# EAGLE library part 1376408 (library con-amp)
DDR1 & DDR2 SODIMM SOCKET 0.6mm Pitch 200 Pos. Standard Profile, Standard Type (used on Kontron X-Board) Source: http://catalog.tycoelectronics.com .. JPN_CD_1376408_S.pdf
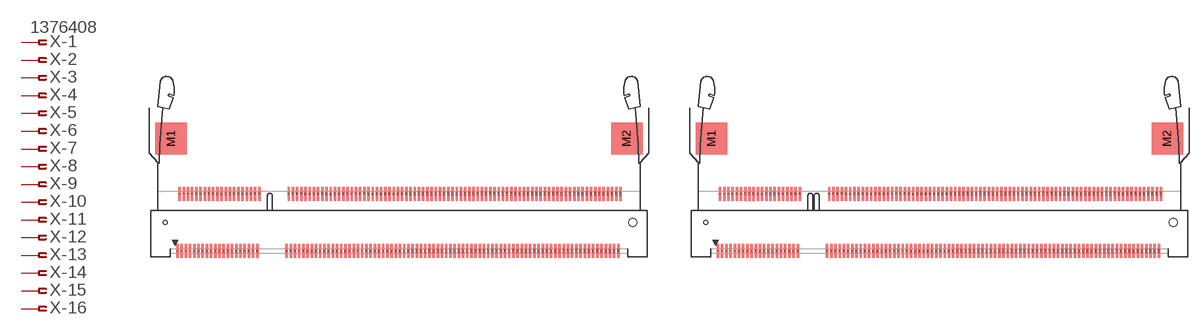
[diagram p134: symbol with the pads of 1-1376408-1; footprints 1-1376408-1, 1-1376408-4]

Designator prefix X; gates -1=PIN-FV -2=PIN-F -3=PIN-F -4=PIN-F -5=PIN-F -6=PIN-F -7=PIN-F -8=PIN-F -9=PIN-F -10=PIN-F -11=PIN-F -12=PIN-F -13=PIN-F -14=PIN-F -15=PIN-F -16=PIN-F -17=PIN-F -18=PIN-F -19=PIN-F -20=PIN-F -21=PIN-F -22=PIN-F -23=PIN-F -24=PIN-F -25=PIN-F -26=PIN-F -27=PIN-F -28=PIN-F -29=PIN-F -30=PIN-F -31=PIN-F -32=PIN-F -33=PIN-F -34=PIN-F -35=PIN-F -36=PIN-F -37=PIN-F -38=PIN-F -39=PIN-F -40=PIN-F -41=PIN-F -42=PIN-F -43=PIN-F -44=PIN-F -45=PIN-F -46=PIN-F -47=PIN-F -48=PIN-F -49=PIN-F -50=PIN-F -51=PIN-F -52=PIN-F -53=PIN-F -54=PIN-F -55=PIN-F -56=PIN-F -57=PIN-F -58=PIN-F -59=PIN-F -60=PIN-F -61=PIN-F -62=PIN-F -63=PIN-F -64=PIN-F -65=PIN-F -66=PIN-F -67=PIN-F -68=PIN-F -69=PIN-F -70=PIN-F -71=PIN-F -72=PIN-F -73=PIN-F -74=PIN-F -75=PIN-F -76=PIN-F -77=PIN-F -78=PIN-F -79=PIN-F -80=PIN-F -81=PIN-F -82=PIN-F -83=PIN-F -84=PIN-F -85=PIN-F -86=PIN-F -87=PIN-F -88=PIN-F -89=PIN-F -90=PIN-F -91=PIN-F -92=PIN-F -93=PIN-F -94=PIN-F -95=PIN-F -96=PIN-F -97=PIN-F -98=PIN-F -99=PIN-F -100=PIN-F -101=PIN-F -102=PIN-F -103=PIN-F -104=PIN-F -105=PIN-F -106=PIN-F -107=PIN-F -108=PIN-F -109=PIN-F -110=PIN-F -111=PIN-F -112=PIN-F -113=PIN-F -114=PIN-F -115=PIN-F -116=PIN-F -117=PIN-F -118=PIN-F -119=PIN-F -120=PIN-F -121=PIN-F -122=PIN-F -123=PIN-F -124=PIN-F -125=PIN-F -126=PIN-F -127=PIN-F -128=PIN-F -129=PIN-F -130=PIN-F -131=PIN-F -132=PIN-F -133=PIN-F -134=PIN-F -135=PIN-F -136=PIN-F -137=PIN-F -138=PIN-F -139=PIN-F -140=PIN-F -141=PIN-F -142=PIN-F -143=PIN-F -144=PIN-F -145=PIN-F -146=PIN-F -147=PIN-F -148=PIN-F -149=PIN-F -150=PIN-F -151=PIN-F -152=PIN-F -153=PIN-F -154=PIN-F -155=PIN-F -156=PIN-F -157=PIN-F -158=PIN-F -159=PIN-F -160=PIN-F -161=PIN-F -162=PIN-F -163=PIN-F -164=PIN-F -165=PIN-F -166=PIN-F -167=PIN-F -168=PIN-F -169=PIN-F -170=PIN-F -171=PIN-F -172=PIN-F -173=PIN-F -174=PIN-F -175=PIN-F -176=PIN-F -177=PIN-F -178=PIN-F -179=PIN-F -180=PIN-F -181=PIN-F -182=PIN-F -183=PIN-F -184=PIN-F -185=PIN-F -186=PIN-F -187=PIN-F -188=PIN-F -189=PIN-F -190=PIN-F -191=PIN-F -192=PIN-F -193=PIN-F -194=PIN-F -195=PIN-F -196=PIN-F -197=PIN-F -198=PIN-F -199=PIN-F -200=PIN-F

## 1376408-1_DDR1_1.8V (MF: TYCO ELECTRONICS; MPN: 1376408-1; OC_FARNELL: unknown; OC_NEWARK: 89C2464)  [1-1376408-1]
1  -1:1  pas
2  -2:1  pas
3  -3:1  pas
4  -4:1  pas
5  -5:1  pas
6  -6:1  pas
7  -7:1  pas
8  -8:1  pas
9  -9:1  pas
10  -10:1  pas
11  -11:1  pas
12  -12:1  pas
13  -13:1  pas
14  -14:1  pas
15  -15:1  pas
16  -16:1  pas
17  -17:1  pas
18  -18:1  pas
19  -19:1  pas
20  -20:1  pas
21  -21:1  pas
22  -22:1  pas
23  -23:1  pas
24  -24:1  pas
25  -25:1  pas
26  -26:1  pas
27  -27:1  pas
28  -28:1  pas
29  -29:1  pas
30  -30:1  pas
31  -31:1  pas
32  -32:1  pas
33  -33:1  pas
34  -34:1  pas
35  -35:1  pas
36  -36:1  pas
37  -37:1  pas
38  -38:1  pas
39  -39:1  pas
40  -40:1  pas
41  -41:1  pas
42  -42:1  pas
43  -43:1  pas
44  -44:1  pas
45  -45:1  pas
46  -46:1  pas
47  -47:1  pas
48  -48:1  pas
49  -49:1  pas
50  -50:1  pas
51  -51:1  pas
52  -52:1  pas
53  -53:1  pas
54  -54:1  pas
55  -55:1  pas
56  -56:1  pas
57  -57:1  pas
58  -58:1  pas
59  -59:1  pas
60  -60:1  pas
61  -61:1  pas
62  -62:1  pas
63  -63:1  pas
64  -64:1  pas
65  -65:1  pas
66  -66:1  pas
67  -67:1  pas
68  -68:1  pas
69  -69:1  pas
70  -70:1  pas
71  -71:1  pas
72  -72:1  pas
73  -73:1  pas
74  -74:1  pas
75  -75:1  pas
76  -76:1  pas
77  -77:1  pas
78  -78:1  pas
79  -79:1  pas
80  -80:1  pas
81  -81:1  pas
82  -82:1  pas
83  -83:1  pas
84  -84:1  pas
85  -85:1  pas
86  -86:1  pas
87  -87:1  pas
88  -88:1  pas
89  -89:1  pas
90  -90:1  pas
91  -91:1  pas
92  -92:1  pas
93  -93:1  pas
94  -94:1  pas
95  -95:1  pas
96  -96:1  pas
97  -97:1  pas
98  -98:1  pas
99  -99:1  pas
100  -100:1  pas
101  -101:1  pas
102  -102:1  pas
103  -103:1  pas
104  -104:1  pas
105  -105:1  pas
106  -106:1  pas
107  -107:1  pas
108  -108:1  pas
109  -109:1  pas
110  -110:1  pas
111  -111:1  pas
112  -112:1  pas
113  -113:1  pas
114  -114:1  pas
115  -115:1  pas
116  -116:1  pas
117  -117:1  pas
118  -118:1  pas
119  -119:1  pas
120  -120:1  pas
121  -121:1  pas
122  -122:1  pas
123  -123:1  pas
124  -124:1  pas
125  -125:1  pas
126  -126:1  pas
127  -127:1  pas
128  -128:1  pas
129  -129:1  pas
130  -130:1  pas
131  -131:1  pas
132  -132:1  pas
133  -133:1  pas
134  -134:1  pas
135  -135:1  pas
136  -136:1  pas
137  -137:1  pas
138  -138:1  pas
139  -139:1  pas
140  -140:1  pas
141  -141:1  pas
142  -142:1  pas
143  -143:1  pas
144  -144:1  pas
145  -145:1  pas
146  -146:1  pas
147  -147:1  pas
148  -148:1  pas
149  -149:1  pas
150  -150:1  pas
151  -151:1  pas
152  -152:1  pas
153  -153:1  pas
154  -154:1  pas
155  -155:1  pas
156  -156:1  pas
157  -157:1  pas
158  -158:1  pas
159  -159:1  pas
160  -160:1  pas
161  -161:1  pas
162  -162:1  pas
163  -163:1  pas
164  -164:1  pas
165  -165:1  pas
166  -166:1  pas
167  -167:1  pas
168  -168:1  pas
169  -169:1  pas
170  -170:1  pas
171  -171:1  pas
172  -172:1  pas
173  -173:1  pas
174  -174:1  pas
175  -175:1  pas
176  -176:1  pas
177  -177:1  pas
178  -178:1  pas
179  -179:1  pas
180  -180:1  pas
181  -181:1  pas
182  -182:1  pas
183  -183:1  pas
184  -184:1  pas
185  -185:1  pas
186  -186:1  pas
187  -187:1  pas
188  -188:1  pas
189  -189:1  pas
190  -190:1  pas
191  -191:1  pas
192  -192:1  pas
193  -193:1  pas
194  -194:1  pas
195  -195:1  pas
196  -196:1  pas
197  -197:1  pas
198  -198:1  pas
199  -199:1  pas
200  -200:1  pas

## 1376408-4_DDR2_2.5V (OC_FARNELL: unknown; OC_NEWARK: unknown)  [1-1376408-4]
Pads as for 1-1376408-1

## 1376408-1_DDR2_2.5V (MF: TYCO ELECTRONICS; MPN: 1376408-1; OC_FARNELL: unknown; OC_NEWARK: 89C2464)  [6-1376408-1]
Pads as for 1-1376408-1

## 1376408-SLOT_1.8V (MF: TYCO ELECTRONICS; MPN: 1376408-1; OC_FARNELL: unknown; OC_NEWARK: 89C2464)  [SLOT-1376408-1_1.8V]
Pads as for 1-1376408-1

## 1376408-SLOT_2.5V (MF: TYCO ELECTRONICS; MPN: 1376408-1; OC_FARNELL: unknown; OC_NEWARK: 89C2464)  [SLOT-1376408-1_2.5V]
Pads as for 1-1376408-1

## Footprint 1-1376408-1 (pad centres in mm)
DDR1 SODIMM SOCKET 0.6mm Pitch 200 Pos. Connector for Kontron X-Board 1.8V Source: http://catalog.tycoelectronics.com ... JPN_CD_1376408_S.pdf
smd 0.35 x 2: 1 -32.65,-4.1; 2 -32.35,4.1; 3 -32.05,-4.1; 4 -31.75,4.1; 5 -31.45,-4.1; 6 -31.15,4.1; 7 -30.85,-4.1; 8 -30.55,4.1; 9 -30.25,-4.1; 10 -29.95,4.1; 11 -29.65,-4.1; 12 -29.35,4.1; 13 -29.05,-4.1; 14 -28.75,4.1; 15 -28.45,-4.1; 16 -28.15,4.1; 17 -27.85,-4.1; 18 -27.55,4.1; 19 -27.25,-4.1; 20 -26.95,4.1; 21 -26.65,-4.1; 22 -26.35,4.1; 23 -26.05,-4.1; 24 -25.75,4.1; 25 -25.45,-4.1; 26 -25.15,4.1; 27 -24.85,-4.1; 28 -24.55,4.1; 29 -24.25,-4.1; 30 -23.95,4.1; 31 -23.65,-4.1; 32 -23.35,4.1; 33 -23.05,-4.1; 34 -22.75,4.1; 35 -22.45,-4.1; 36 -22.15,4.1; 37 -21.85,-4.1; 38 -21.55,4.1; 39 -21.25,-4.1; 40 -20.95,4.1; 41 -17.05,-4.1; 42 -16.75,4.1; 43 -16.45,-4.1; 44 -16.15,4.1; 45 -15.85,-4.1; 46 -15.55,4.1; 47 -15.25,-4.1; 48 -14.95,4.1; 49 -14.65,-4.1; 50 -14.35,4.1; 51 -14.05,-4.1; 52 -13.75,4.1; 53 -13.45,-4.1; 54 -13.15,4.1; 55 -12.85,-4.1; 56 -12.55,4.1; 57 -12.25,-4.1; 58 -11.95,4.1; 59 -11.65,-4.1; 60 -11.35,4.1; 61 -11.05,-4.1; 62 -10.75,4.1; 63 -10.45,-4.1; 64 -10.15,4.1; 65 -9.85,-4.1; 66 -9.55,4.1; 67 -9.25,-4.1; 68 -8.95,4.1; 69 -8.65,-4.1; 70 -8.35,4.1; 71 -8.05,-4.1; 72 -7.75,4.1; 73 -7.45,-4.1; 74 -7.15,4.1; 75 -6.85,-4.1; 76 -6.55,4.1; 77 -6.25,-4.1; 78 -5.95,4.1; 79 -5.65,-4.1; 80 -5.35,4.1; 81 -5.05,-4.1; 82 -4.75,4.1; 83 -4.45,-4.1; 84 -4.15,4.1; 85 -3.85,-4.1; 86 -3.55,4.1; 87 -3.25,-4.1; 88 -2.95,4.1; 89 -2.65,-4.1; 90 -2.35,4.1; 91 -2.05,-4.1; 92 -1.75,4.1; 93 -1.45,-4.1; 94 -1.15,4.1; 95 -0.85,-4.1; 96 -0.55,4.1; 97 -0.25,-4.1; 98 0.05,4.1; 99 0.35,-4.1; 100 0.65,4.1; 101 0.95,-4.1; 102 1.25,4.1; 103 1.55,-4.1; 104 1.85,4.1; 105 2.15,-4.1; 106 2.45,4.1; 107 2.75,-4.1; 108 3.05,4.1; 109 3.35,-4.1; 110 3.65,4.1; 111 3.95,-4.1; 112 4.25,4.1; 113 4.55,-4.1; 114 4.85,4.1; 115 5.15,-4.1; 116 5.45,4.1; 117 5.75,-4.1; 118 6.05,4.1; 119 6.35,-4.1; 120 6.65,4.1; 121 6.95,-4.1; 122 7.25,4.1; 123 7.55,-4.1; 124 7.85,4.1; 125 8.15,-4.1; 126 8.45,4.1; 127 8.75,-4.1; 128 9.05,4.1; 129 9.35,-4.1; 130 9.65,4.1; 131 9.95,-4.1; 132 10.25,4.1; 133 10.55,-4.1; 134 10.85,4.1; 135 11.15,-4.1; 136 11.45,4.1; 137 11.75,-4.1; 138 12.05,4.1; 139 12.35,-4.1; 140 12.65,4.1; 141 12.95,-4.1; 142 13.25,4.1; 143 13.55,-4.1; 144 13.85,4.1; 145 14.15,-4.1; 146 14.45,4.1; 147 14.75,-4.1; 148 15.05,4.1; 149 15.35,-4.1; 150 15.65,4.1; 151 15.95,-4.1; 152 16.25,4.1; 153 16.55,-4.1; 154 16.85,4.1; 155 17.15,-4.1; 156 17.45,4.1; 157 17.75,-4.1; 158 18.05,4.1; 159 18.35,-4.1; 160 18.65,4.1; 161 18.95,-4.1; 162 19.25,4.1; 163 19.55,-4.1; 164 19.85,4.1; 165 20.15,-4.1; 166 20.45,4.1; 167 20.75,-4.1; 168 21.05,4.1; 169 21.35,-4.1; 170 21.65,4.1; 171 21.95,-4.1; 172 22.25,4.1; 173 22.55,-4.1; 174 22.85,4.1; 175 23.15,-4.1; 176 23.45,4.1; 177 23.75,-4.1; 178 24.05,4.1; 179 24.35,-4.1; 180 24.65,4.1; 181 24.95,-4.1; 182 25.25,4.1; 183 25.55,-4.1; 184 25.85,4.1; 185 26.15,-4.1; 186 26.45,4.1; 187 26.75,-4.1; 188 27.05,4.1; 189 27.35,-4.1; 190 27.65,4.1; 191 27.95,-4.1; 192 28.25,4.1; 193 28.55,-4.1; 194 28.85,4.1; 195 29.15,-4.1; 196 29.45,4.1; 197 29.75,-4.1; 198 30.05,4.1; 199 30.35,-4.1; 200 30.65,4.1
smd 4.5 x 4.6: M1 -33.55,12; M2 31.55,12
hole 0.6 at -34.4,0
hole 1.1 at 32.4,0

## Footprint 1-1376408-4 (pad centres in mm)
DDR2 SODIMM SOCKET 0.6mm Pitch 200 Pos. Connector for Kontron X-Board 2.5V Source: http://catalog.tycoelectronics.com ... JPN_CD_1376408_S.pdf
smd 0.35 x 2: 1 -32.65,-4.1; 2 -32.35,4.1; 3 -32.05,-4.1; 4 -31.75,4.1; 5 -31.45,-4.1; 6 -31.15,4.1; 7 -30.85,-4.1; 8 -30.55,4.1; 9 -30.25,-4.1; 10 -29.95,4.1; 11 -29.65,-4.1; 12 -29.35,4.1; 13 -29.05,-4.1; 14 -28.75,4.1; 15 -28.45,-4.1; 16 -28.15,4.1; 17 -27.85,-4.1; 18 -27.55,4.1; 19 -27.25,-4.1; 20 -26.95,4.1; 21 -26.65,-4.1; 22 -26.35,4.1; 23 -26.05,-4.1; 24 -25.75,4.1; 25 -25.45,-4.1; 26 -25.15,4.1; 27 -24.85,-4.1; 28 -24.55,4.1; 29 -24.25,-4.1; 30 -23.95,4.1; 31 -23.65,-4.1; 32 -23.35,4.1; 33 -23.05,-4.1; 34 -22.75,4.1; 35 -22.45,-4.1; 36 -22.15,4.1; 37 -21.85,-4.1; 38 -21.55,4.1; 39 -21.25,-4.1; 40 -20.95,4.1; 41 -17.05,-4.1; 42 -16.75,4.1; 43 -16.45,-4.1; 44 -16.15,4.1; 45 -15.85,-4.1; 46 -15.55,4.1; 47 -15.25,-4.1; 48 -14.95,4.1; 49 -14.65,-4.1; 50 -14.35,4.1; 51 -14.05,-4.1; 52 -13.75,4.1; 53 -13.45,-4.1; 54 -13.15,4.1; 55 -12.85,-4.1; 56 -12.55,4.1; 57 -12.25,-4.1; 58 -11.95,4.1; 59 -11.65,-4.1; 60 -11.35,4.1; 61 -11.05,-4.1; 62 -10.75,4.1; 63 -10.45,-4.1; 64 -10.15,4.1; 65 -9.85,-4.1; 66 -9.55,4.1; 67 -9.25,-4.1; 68 -8.95,4.1; 69 -8.65,-4.1; 70 -8.35,4.1; 71 -8.05,-4.1; 72 -7.75,4.1; 73 -7.45,-4.1; 74 -7.15,4.1; 75 -6.85,-4.1; 76 -6.55,4.1; 77 -6.25,-4.1; 78 -5.95,4.1; 79 -5.65,-4.1; 80 -5.35,4.1; 81 -5.05,-4.1; 82 -4.75,4.1; 83 -4.45,-4.1; 84 -4.15,4.1; 85 -3.85,-4.1; 86 -3.55,4.1; 87 -3.25,-4.1; 88 -2.95,4.1; 89 -2.65,-4.1; 90 -2.35,4.1; 91 -2.05,-4.1; 92 -1.75,4.1; 93 -1.45,-4.1; 94 -1.15,4.1; 95 -0.85,-4.1; 96 -0.55,4.1; 97 -0.25,-4.1; 98 0.05,4.1; 99 0.35,-4.1; 100 0.65,4.1; 101 0.95,-4.1; 102 1.25,4.1; 103 1.55,-4.1; 104 1.85,4.1; 105 2.15,-4.1; 106 2.45,4.1; 107 2.75,-4.1; 108 3.05,4.1; 109 3.35,-4.1; 110 3.65,4.1; 111 3.95,-4.1; 112 4.25,4.1; 113 4.55,-4.1; 114 4.85,4.1; 115 5.15,-4.1; 116 5.45,4.1; 117 5.75,-4.1; 118 6.05,4.1; 119 6.35,-4.1; 120 6.65,4.1; 121 6.95,-4.1; 122 7.25,4.1; 123 7.55,-4.1; 124 7.85,4.1; 125 8.15,-4.1; 126 8.45,4.1; 127 8.75,-4.1; 128 9.05,4.1; 129 9.35,-4.1; 130 9.65,4.1; 131 9.95,-4.1; 132 10.25,4.1; 133 10.55,-4.1; 134 10.85,4.1; 135 11.15,-4.1; 136 11.45,4.1; 137 11.75,-4.1; 138 12.05,4.1; 139 12.35,-4.1; 140 12.65,4.1; 141 12.95,-4.1; 142 13.25,4.1; 143 13.55,-4.1; 144 13.85,4.1; 145 14.15,-4.1; 146 14.45,4.1; 147 14.75,-4.1; 148 15.05,4.1; 149 15.35,-4.1; 150 15.65,4.1; 151 15.95,-4.1; 152 16.25,4.1; 153 16.55,-4.1; 154 16.85,4.1; 155 17.15,-4.1; 156 17.45,4.1; 157 17.75,-4.1; 158 18.05,4.1; 159 18.35,-4.1; 160 18.65,4.1; 161 18.95,-4.1; 162 19.25,4.1; 163 19.55,-4.1; 164 19.85,4.1; 165 20.15,-4.1; 166 20.45,4.1; 167 20.75,-4.1; 168 21.05,4.1; 169 21.35,-4.1; 170 21.65,4.1; 171 21.95,-4.1; 172 22.25,4.1; 173 22.55,-4.1; 174 22.85,4.1; 175 23.15,-4.1; 176 23.45,4.1; 177 23.75,-4.1; 178 24.05,4.1; 179 24.35,-4.1; 180 24.65,4.1; 181 24.95,-4.1; 182 25.25,4.1; 183 25.55,-4.1; 184 25.85,4.1; 185 26.15,-4.1; 186 26.45,4.1; 187 26.75,-4.1; 188 27.05,4.1; 189 27.35,-4.1; 190 27.65,4.1; 191 27.95,-4.1; 192 28.25,4.1; 193 28.55,-4.1; 194 28.85,4.1; 195 29.15,-4.1; 196 29.45,4.1; 197 29.75,-4.1; 198 30.05,4.1; 199 30.35,-4.1; 200 30.65,4.1
smd 4.5 x 4.6: M1 -33.55,12; M2 31.55,12
hole 0.6 at -34.4,0
hole 1.1 at 32.4,0

## Footprint 6-1376408-1 (pad centres in mm)
DDR2 SODIMM SOCKET 0.6mm Pitch 200 Pos. Connector for Kontron X-Board 2.5V Source: http://catalog.tycoelectronics.com ... JPN_CD_1376408_S.pdf
smd 0.35 x 2: 1 -32.65,-4.1; 2 -32.35,4.1; 3 -32.05,-4.1; 4 -31.75,4.1; 5 -31.45,-4.1; 6 -31.15,4.1; 7 -30.85,-4.1; 8 -30.55,4.1; 9 -30.25,-4.1; 10 -29.95,4.1; 11 -29.65,-4.1; 12 -29.35,4.1; 13 -29.05,-4.1; 14 -28.75,4.1; 15 -28.45,-4.1; 16 -28.15,4.1; 17 -27.85,-4.1; 18 -27.55,4.1; 19 -27.25,-4.1; 20 -26.95,4.1; 21 -26.65,-4.1; 22 -26.35,4.1; 23 -26.05,-4.1; 24 -25.75,4.1; 25 -25.45,-4.1; 26 -25.15,4.1; 27 -24.85,-4.1; 28 -24.55,4.1; 29 -24.25,-4.1; 30 -23.95,4.1; 31 -23.65,-4.1; 32 -23.35,4.1; 33 -23.05,-4.1; 34 -22.75,4.1; 35 -22.45,-4.1; 36 -22.15,4.1; 37 -21.85,-4.1; 38 -21.55,4.1; 39 -21.25,-4.1; 40 -20.95,4.1; 41 -17.05,-4.1; 42 -16.75,4.1; 43 -16.45,-4.1; 44 -16.15,4.1; 45 -15.85,-4.1; 46 -15.55,4.1; 47 -15.25,-4.1; 48 -14.95,4.1; 49 -14.65,-4.1; 50 -14.35,4.1; 51 -14.05,-4.1; 52 -13.75,4.1; 53 -13.45,-4.1; 54 -13.15,4.1; 55 -12.85,-4.1; 56 -12.55,4.1; 57 -12.25,-4.1; 58 -11.95,4.1; 59 -11.65,-4.1; 60 -11.35,4.1; 61 -11.05,-4.1; 62 -10.75,4.1; 63 -10.45,-4.1; 64 -10.15,4.1; 65 -9.85,-4.1; 66 -9.55,4.1; 67 -9.25,-4.1; 68 -8.95,4.1; 69 -8.65,-4.1; 70 -8.35,4.1; 71 -8.05,-4.1; 72 -7.75,4.1; 73 -7.45,-4.1; 74 -7.15,4.1; 75 -6.85,-4.1; 76 -6.55,4.1; 77 -6.25,-4.1; 78 -5.95,4.1; 79 -5.65,-4.1; 80 -5.35,4.1; 81 -5.05,-4.1; 82 -4.75,4.1; 83 -4.45,-4.1; 84 -4.15,4.1; 85 -3.85,-4.1; 86 -3.55,4.1; 87 -3.25,-4.1; 88 -2.95,4.1; 89 -2.65,-4.1; 90 -2.35,4.1; 91 -2.05,-4.1; 92 -1.75,4.1; 93 -1.45,-4.1; 94 -1.15,4.1; 95 -0.85,-4.1; 96 -0.55,4.1; 97 -0.25,-4.1; 98 0.05,4.1; 99 0.35,-4.1; 100 0.65,4.1; 101 0.95,-4.1; 102 1.25,4.1; 103 1.55,-4.1; 104 1.85,4.1; 105 2.15,-4.1; 106 2.45,4.1; 107 2.75,-4.1; 108 3.05,4.1; 109 3.35,-4.1; 110 3.65,4.1; 111 3.95,-4.1; 112 4.25,4.1; 113 4.55,-4.1; 114 4.85,4.1; 115 5.15,-4.1; 116 5.45,4.1; 117 5.75,-4.1; 118 6.05,4.1; 119 6.35,-4.1; 120 6.65,4.1; 121 6.95,-4.1; 122 7.25,4.1; 123 7.55,-4.1; 124 7.85,4.1; 125 8.15,-4.1; 126 8.45,4.1; 127 8.75,-4.1; 128 9.05,4.1; 129 9.35,-4.1; 130 9.65,4.1; 131 9.95,-4.1; 132 10.25,4.1; 133 10.55,-4.1; 134 10.85,4.1; 135 11.15,-4.1; 136 11.45,4.1; 137 11.75,-4.1; 138 12.05,4.1; 139 12.35,-4.1; 140 12.65,4.1; 141 12.95,-4.1; 142 13.25,4.1; 143 13.55,-4.1; 144 13.85,4.1; 145 14.15,-4.1; 146 14.45,4.1; 147 14.75,-4.1; 148 15.05,4.1; 149 15.35,-4.1; 150 15.65,4.1; 151 15.95,-4.1; 152 16.25,4.1; 153 16.55,-4.1; 154 16.85,4.1; 155 17.15,-4.1; 156 17.45,4.1; 157 17.75,-4.1; 158 18.05,4.1; 159 18.35,-4.1; 160 18.65,4.1; 161 18.95,-4.1; 162 19.25,4.1; 163 19.55,-4.1; 164 19.85,4.1; 165 20.15,-4.1; 166 20.45,4.1; 167 20.75,-4.1; 168 21.05,4.1; 169 21.35,-4.1; 170 21.65,4.1; 171 21.95,-4.1; 172 22.25,4.1; 173 22.55,-4.1; 174 22.85,4.1; 175 23.15,-4.1; 176 23.45,4.1; 177 23.75,-4.1; 178 24.05,4.1; 179 24.35,-4.1; 180 24.65,4.1; 181 24.95,-4.1; 182 25.25,4.1; 183 25.55,-4.1; 184 25.85,4.1; 185 26.15,-4.1; 186 26.45,4.1; 187 26.75,-4.1; 188 27.05,4.1; 189 27.35,-4.1; 190 27.65,4.1; 191 27.95,-4.1; 192 28.25,4.1; 193 28.55,-4.1; 194 28.85,4.1; 195 29.15,-4.1; 196 29.45,4.1; 197 29.75,-4.1; 198 30.05,4.1; 199 30.35,-4.1; 200 30.65,4.1
smd 4.5 x 4.6: M1 -33.55,12; M2 31.55,12
hole 0.6 at -34.4,0
hole 1.1 at 32.4,0

## Footprint SLOT-1376408-1_1.8V (pad centres in mm)
DDR1 & DDR2 SODIMM SOCKET1.8V 0.6mm Pitch 200 Pos. Standard Prfile DStandard Type Source: http://catalog.tycoelectronics.com .. JPN_CD_1376408_S.pdf
smd 0.45 x 2.3: 1 2.15,1.4; 3 2.75,1.4; 5 3.35,1.4; 7 3.95,1.4; 9 4.55,1.4; 11 5.15,1.4; 13 5.75,1.4; 15 6.35,1.4; 17 6.95,1.4; 19 7.55,1.4; 21 8.15,1.4; 23 8.75,1.4; 25 9.35,1.4; 27 9.95,1.4; 29 10.55,1.4; 31 11.15,1.4; 33 11.75,1.4; 35 12.35,1.4; 37 12.95,1.4; 39 13.55,1.4; 41 17.75,1.4; 43 18.35,1.4; 45 18.95,1.4; 47 19.55,1.4; 49 20.15,1.4; 51 20.75,1.4; 53 21.35,1.4; 55 21.95,1.4; 57 22.55,1.4; 59 23.15,1.4; 61 23.75,1.4; 63 24.35,1.4; 65 24.95,1.4; 67 25.55,1.4; 69 26.15,1.4; 71 26.75,1.4; 73 27.35,1.4; 75 27.95,1.4; 77 28.55,1.4; 79 29.15,1.4; 81 29.75,1.4; 83 30.35,1.4; 85 30.95,1.4; 87 31.55,1.4; 89 32.15,1.4; 91 32.75,1.4; 93 33.35,1.4; 95 33.95,1.4; 97 34.55,1.4; 99 35.15,1.4; 101 35.75,1.4; 103 36.35,1.4; 105 36.95,1.4; 107 37.55,1.4; 109 38.15,1.4; 111 38.75,1.4; 113 39.35,1.4; 115 39.95,1.4; 117 40.55,1.4; 119 41.15,1.4; 121 41.75,1.4; 123 42.35,1.4; 125 42.95,1.4; 127 43.55,1.4; 129 44.15,1.4; 131 44.75,1.4; 133 45.35,1.4; 135 45.95,1.4; 137 46.55,1.4; 139 47.15,1.4; 141 47.75,1.4; 143 48.35,1.4; 145 48.95,1.4; 147 49.55,1.4; 149 50.15,1.4; 151 50.75,1.4; 153 51.35,1.4; 155 51.95,1.4; 157 52.55,1.4; 159 53.15,1.4; 161 53.75,1.4; 163 54.35,1.4; 165 54.95,1.4; 167 55.55,1.4; 169 56.15,1.4; 171 56.75,1.4; 173 57.35,1.4; 175 57.95,1.4; 177 58.55,1.4; 179 59.15,1.4; 181 59.75,1.4; 183 60.35,1.4; 185 60.95,1.4; 187 61.55,1.4; 189 62.15,1.4; 191 62.75,1.4; 193 63.35,1.4; 195 63.95,1.4; 197 64.55,1.4; 199 65.15,1.4
smd 0.45 x 2.3 bottom: 2 2.15,1.4; 4 2.75,1.4; 6 3.35,1.4; 8 3.95,1.4; 10 4.55,1.4; 12 5.15,1.4; 14 5.75,1.4; 16 6.35,1.4; 18 6.95,1.4; 20 7.55,1.4; 22 8.15,1.4; 24 8.75,1.4; 26 9.35,1.4; 28 9.95,1.4; 30 10.55,1.4; 32 11.15,1.4; 34 11.75,1.4; 36 12.35,1.4; 38 12.95,1.4; 40 13.55,1.4; 42 17.75,1.4; 44 18.35,1.4; 46 18.95,1.4; 48 19.55,1.4; 50 20.15,1.4; 52 20.75,1.4; 54 21.35,1.4; 56 21.95,1.4; 58 22.55,1.4; 60 23.15,1.4; 62 23.75,1.4; 64 24.35,1.4; 66 24.95,1.4; 68 25.55,1.4; 70 26.15,1.4; 72 26.75,1.4; 74 27.35,1.4; 76 27.95,1.4; 78 28.55,1.4; 80 29.15,1.4; 82 29.75,1.4; 84 30.35,1.4; 86 30.95,1.4; 88 31.55,1.4; 90 32.15,1.4; 92 32.75,1.4; 94 33.35,1.4; 96 33.95,1.4; 98 34.55,1.4; 100 35.15,1.4; 102 35.75,1.4; 104 36.35,1.4; 106 36.95,1.4; 108 37.55,1.4; 110 38.15,1.4; 112 38.75,1.4; 114 39.35,1.4; 116 39.95,1.4; 118 40.55,1.4; 120 41.15,1.4; 122 41.75,1.4; 124 42.35,1.4; 126 42.95,1.4; 128 43.55,1.4; 130 44.15,1.4; 132 44.75,1.4; 134 45.35,1.4; 136 45.95,1.4; 138 46.55,1.4; 140 47.15,1.4; 142 47.75,1.4; 144 48.35,1.4; 146 48.95,1.4; 148 49.55,1.4; 150 50.15,1.4; 152 50.75,1.4; 154 51.35,1.4; 156 51.95,1.4; 158 52.55,1.4; 160 53.15,1.4; 162 53.75,1.4; 164 54.35,1.4; 166 54.95,1.4; 168 55.55,1.4; 170 56.15,1.4; 172 56.75,1.4; 174 57.35,1.4; 176 57.95,1.4; 178 58.55,1.4; 180 59.15,1.4; 182 59.75,1.4; 184 60.35,1.4; 186 60.95,1.4; 188 61.55,1.4; 190 62.15,1.4; 192 62.75,1.4; 194 63.35,1.4; 196 63.95,1.4; 198 64.55,1.4; 200 65.15,1.4
hole 1.8 at 2.15,6
hole 1.8 at 65.75,6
